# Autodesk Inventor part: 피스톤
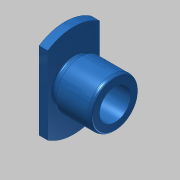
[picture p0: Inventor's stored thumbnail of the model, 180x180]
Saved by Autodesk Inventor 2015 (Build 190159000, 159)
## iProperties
Created: 2019-02
Part Number: 피스톤
Material: 알루미늄 6061
Document SubType Name: Modeling
Designer: mduedu
Density: 1 g/cm^3
Appearance: 청록색
Author: mduedu
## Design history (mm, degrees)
sketch "스케치1"
  geometry: C1 r 27 at (0, 0); 1 further point
  constraints: 1 centre point, 1 coincident
  dimensions: "d0" = 54 diameter of C1
extrude "돌출1" new body sketch "스케치1" distance "d1" = 5; taper "d2" = 0 deg
sketch "스케치2"
  geometry: L1 (-15, -27)-(15, -27); L2 (15, -27)-(15, 27); L3 (15, 27)-(-15, 27); L4 (-15, 27)-(-15, -27); L5 (-15, -27)-(15, 27); L6 (15, -27)-(-15, 27); C1 r 27 at (0, 0) reference; 1 further point
  constraints: 12 end point, 2 midpoint, 2 parallel, 1 horizontal, 1 perpendicular, 1 tangent
  dimensions: "d3" = 30 distance of L2.end L3.end
extrude "돌출2" sketch "스케치2" stored distance "d5" = 5; taper "d6" = 0 deg
sketch "스케치3"
  geometry: C1 r 12 at (0, 0); 1 further point
  constraints: 1 centre point, 1 coincident
  dimensions: "d7" = 24 diameter of C1
extrude "돌출3" join sketch "스케치3" distance "d8" = 4; taper "d9" = 0 deg
sketch "스케치4"
  geometry: C1 r 14 at (0, 0); 1 further point
  constraints: 1 centre point, 1 coincident
  dimensions: "d10" = 28 diameter of C1
extrude "돌출4" join sketch "스케치4" distance "d11" = 20; taper "d12" = 0 deg
fillet "모깎기1" dims "d13" = 1
chamfer "모따기1" distance "d14" = 1.8; stored, may be unused: second distance "d15" = 2, angle "d16" = 15 deg
fillet "모깎기2" dims "d17" = 1, "d18" = 2
sketch "스케치5"
  geometry: 2 further points
  constraints: 1 coincident
hole "구멍1" sketch "스케치5" at (0, 0) diameter "d19" = 18; stored, may be unused: countersink angle "d23" = 90 deg, drill point angle "d25" = 118 deg; dims "d20" = 6, "d21" = 4, "d22" = 2, "d24" = 15
node "솔리드1"
